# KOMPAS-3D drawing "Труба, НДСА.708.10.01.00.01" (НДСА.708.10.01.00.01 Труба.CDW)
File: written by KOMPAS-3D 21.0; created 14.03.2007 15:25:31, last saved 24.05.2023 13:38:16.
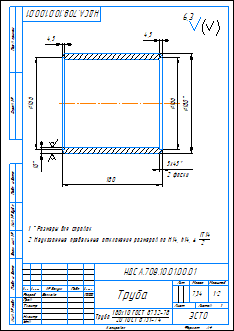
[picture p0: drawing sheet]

Sheet 1: A4, portrait

Document properties: Полное имя файла: C:\Users\s.pischagina\Desktop\PLM\НДСА.708.10.01.00.01 Труба.CDW; Автор: Ширяева О.А.; Организация: Эсто-вакуум; Масса: 7.34; Знак неуказанной шероховатости: 4; Параметр неуказанной шероховатости: 6,3; PDM_DOCXDTO: <item xmlns="http://appius.ru/pdm" xmlns:xs="http://www.w3.org/2001/XMLSchema" xmlns:xsi="http://www.w3.org/2001/XMLSchema-instance" xsi:type="item">  <element xmlns:d2p1="http://v8.1c.ru/8.1/data/enterprise/current-config" xsi:type="d2p1:CatalogRef.aps_Элемен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; PDM_ITEMXDTO: <item xmlns="http://appius.ru/pdm" xmlns:xs="http://www.w3.org/2001/XMLSchema" xmlns:xsi="http://www.w3.org/2001/XMLSchema-instance" xsi:type="item">  <element xmlns:d2p1="http://v8.1c.ru/8.1/data/enterprise/current-config" xsi:type="d2p1:CatalogRef.aps_Элемен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; PDM_DRAWINGXDTO: <item xmlns="http://appius.ru/pdm" xmlns:xs="http://www.w3.org/2001/XMLSchema" xmlns:xsi="http://www.w3.org/2001/XMLSchema-instance" xsi:type="item">  <element xmlns:d2p1="http://v8.1c.ru/8.1/data/enterprise/current-config" xsi:type="d2p1:CatalogRef.aps_Элемен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; PLM_CDWXDTO: <item xmlns="http://appius.ru/pdm" xmlns:xs="http://www.w3.org/2001/XMLSchema" xmlns:xsi="http://www.w3.org/2001/XMLSchema-instance" xsi:type="item">  <element xmlns:d2p1="http://v8.1c.ru/8.1/data/enterprise/current-config" xsi:type="d2p1:CatalogRef.aps_Элемен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

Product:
- Part/product: Труба  | designation НДСА.708.10.01.00.01
    Материал: Труба$d180х10 ГОСТ 8732-78;20 ГОСТ 8731-74$ (density 7859 kg/m3)
    Масса: 7.337365
    Форматы листов документа: A4
    additional columns: <item xmlns="http://appius.ru/pdm" xmlns:xs="http://www.w3.org/2001/XMLSchema" x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; <item xmlns="http://appius.ru/pdm" xmlns:xs="http://www.w3.org/2001/XMLSchema" x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; <item xmlns="http://appius.ru/pdm" xmlns:xs="http://www.w3.org/2001/XMLSchema" x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

Title block, sheet 1: Наименование: Труба; designation: НДСА.708.10.01.00.01; Материал: Труба 180х10 ГОСТ 8732-78 20 ГОСТ 8731-74; Масса: 7,34; scale: 1:2; Количество листов документа: 1; organisation: ЭСТО; Форматы листов документа: A4; stored path: D:\Шлейф\УКРД.762.10.00.00.00 Верхняя стойка\УКРД.762.10.01.00.03 Труба.cdw; Разработал: Волкова; Разработал, date: 17.01.2020
Table, sheet 1:
  0;Material:V399CD8922A934364BF9D3DB1A16B3F75;Sortament:VACA86AD6B524487FA06521D22EE88F1C^SortamentEx:VA444AFA89AC74945B3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

Views: Вид 1, Сверху, Разрез А-А
Referenced files in C:\Users\s.pischagina\Desktop\PLM\: НДСА.708.10.01.00.01 Труба.m3d
Referenced files in E:\НДСА.014.01.09.00.00 Верхняя стойка гидроподъемника\: НДСА.014.01.09.01.02 Труба.m3d
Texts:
  НДСА.708.10.01.00.01 Труба
Dimensions and other numbers on the sheet: 180; 166; 10; 5; 2 фаски; 4,5; 6,3; 1:2; 1; 7,34; 17.01.2020

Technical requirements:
  1. *Размеры для справок.
  2. Неуказанные предельные отклонения размеров по H14, h14,    IT14 2 .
